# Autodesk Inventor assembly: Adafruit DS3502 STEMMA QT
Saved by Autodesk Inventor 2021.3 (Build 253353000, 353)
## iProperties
Created: 2023-09
Part Number: Adafruit DS3502 STEMMA QT
Document SubType Name: Assembly
Designer: AdminForWorker
Title: Adafruit DS3502 STEMMA QT v1
Author: AdminForWorker
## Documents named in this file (8)
- z:\worker\convert-fusion-r04-cosv3\tmp\job-1\2400\output\files\b50e43e6-88dc-4ae4-8798-25d0c03346c5\Adafruit DS3502 STEMMA QT v1.iam
- z:\worker\convert-fusion-r04-cosv3\tmp\job-1\2400\output\files\b50e43e6-88dc-4ae4-8798-25d0c03346c5\Printed Circuit Board.ipt
- z:\worker\convert-fusion-r04-cosv3\tmp\job-1\2400\output\files\b50e43e6-88dc-4ae4-8798-25d0c03346c5\DS3502 Potentiometer 10k Ohm v3.ipt
- z:\worker\convert-fusion-r04-cosv3\tmp\job-1\2400\output\files\b50e43e6-88dc-4ae4-8798-25d0c03346c5\LED 0603 single color v1.ipt
- z:\worker\convert-fusion-r04-cosv3\tmp\job-1\2400\output\files\b50e43e6-88dc-4ae4-8798-25d0c03346c5\CAPC-0603-T0.9-BN v1.ipt
- z:\worker\convert-fusion-r04-cosv3\tmp\job-1\2400\output\files\b50e43e6-88dc-4ae4-8798-25d0c03346c5\RESC-0603 v1.ipt
- z:\worker\convert-fusion-r04-cosv3\tmp\job-1\2400\output\files\b50e43e6-88dc-4ae4-8798-25d0c03346c5\YC164_RESPACK v1.ipt
- z:\worker\convert-fusion-r04-cosv3\tmp\job-1\2400\output\files\b50e43e6-88dc-4ae4-8798-25d0c03346c5\JST SH, 4 Pin v2.ipt
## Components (9 placed, 7 different names)
1. Printed Circuit Board:1
2. DS3502 Potentiometer 10k Ohm v3:1
3. LED 0603 single color v1:1
4. CAPC-0603-T0.9-BN v1:1
5. CAPC-0603-T0.9-BN v1:2
6. RESC-0603 v1:1
7. YC164_RESPACK v1:1
8. JST SH, 4 Pin v2:1
9. JST SH, 4 Pin v2:2
